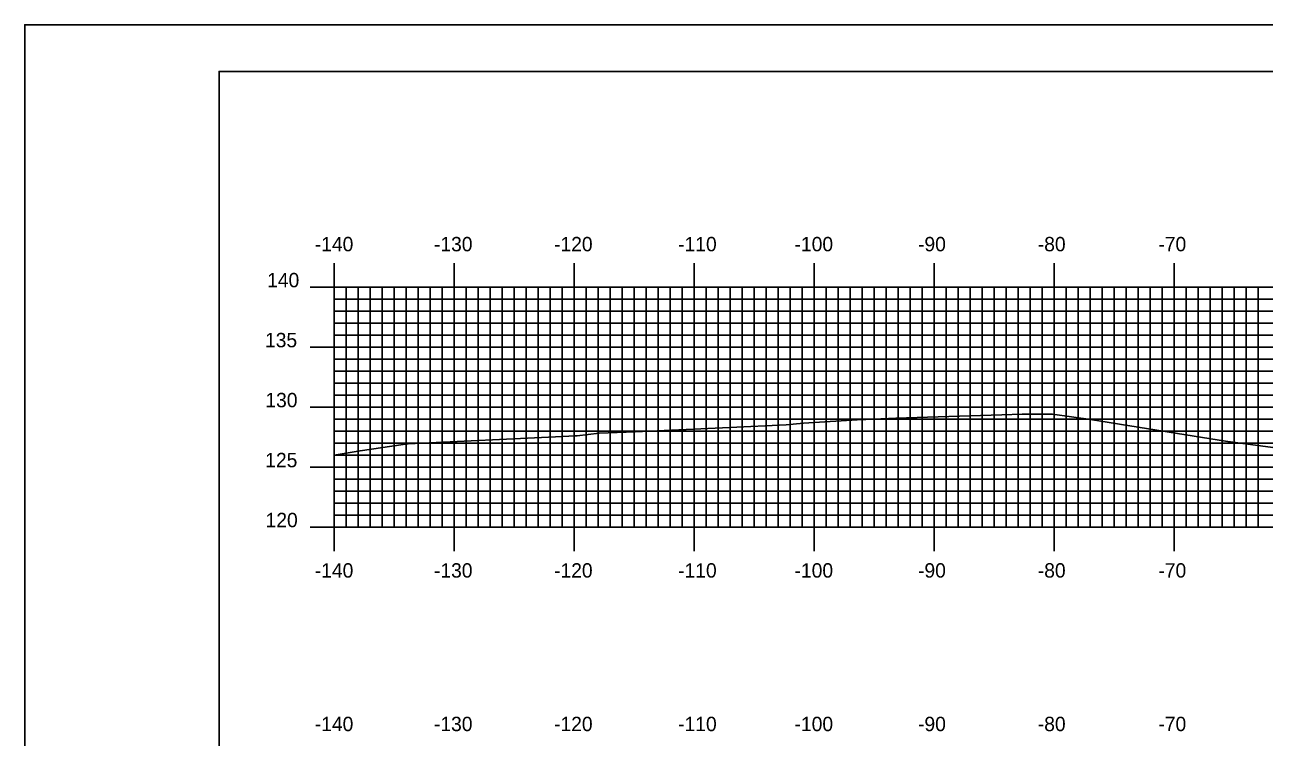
# Model space of a CAD drawing. Extents: x 841388 to 841731, y 363538 to 363758.
# Drawn here: x 841388.1 to 841491.4, y 363698.2 to 363757.6 of the extents above; entities that cross this region are included whole.
import ezdxf

# ---------------------------------------------------------------- set-up
doc = ezdxf.new("R2010")
doc.units = 0
for name, color, linetype in [('BORDER', 7, 'Continuous'), ('H_V ANNOTATION', 7, 'Continuous'), ('M_Roadway_Centerline', 7, 'Continuous'), ('MAJOR', 7, 'Continuous'), ('MINOR', 7, 'Continuous'), ('PLOT BOUNDARY', 7, 'Continuous'), ('S_Roadway_Centerline', 7, 'Continuous')]:
    doc.layers.add(name, color=color, linetype=linetype)

msp = doc.modelspace()

# ---------------------------------------------------------------- linework, layer by layer
at = {"layer": 'BORDER'}
msp.add_lwpolyline([(841404.26, 363543.72), (841724.26, 363543.72), (841724.26, 363753.72), (841404.26, 363753.72)], close=True, dxfattribs=at)
at = {"layer": 'MAJOR'}
for p, q in [((841413.86, 363737.73), (841413.86, 363735.72)), ((841423.86, 363737.73), (841423.86, 363735.72)), ((841433.86, 363737.73), (841433.86, 363735.72)), ((841443.86, 363737.73), (841443.86, 363735.72)), ((841453.86, 363737.73), (841453.86, 363735.72)), ((841463.86, 363737.73), (841463.86, 363735.72)), ((841473.86, 363737.73), (841473.86, 363735.72)), ((841483.86, 363737.73), (841483.86, 363735.72)), ((841411.85, 363735.72), (841413.86, 363735.72)), ((841413.86, 363735.72), (841693.86, 363735.72)), ((841413.86, 363715.72), (841413.86, 363735.72)), ((841413.86, 363715.72), (841413.86, 363735.72)), ((841413.86, 363735.72), (841693.86, 363735.72)), ((841423.86, 363715.72), (841423.86, 363735.72)), ((841433.86, 363715.72), (841433.86, 363735.72)), ((841443.86, 363715.72), (841443.86, 363735.72)), ((841453.86, 363715.72), (841453.86, 363735.72)), ((841463.86, 363715.72), (841463.86, 363735.72)), ((841473.86, 363715.72), (841473.86, 363735.72)), ((841483.86, 363715.72), (841483.86, 363735.72)), ((841411.85, 363730.72), (841413.86, 363730.72)), ((841413.86, 363730.72), (841693.86, 363730.72)), ((841411.85, 363725.72), (841413.86, 363725.72)), ((841413.86, 363725.72), (841693.86, 363725.72)), ((841411.85, 363720.72), (841413.86, 363720.72)), ((841413.86, 363720.72), (841693.86, 363720.72)), ((841411.85, 363715.72), (841413.86, 363715.72)), ((841413.86, 363715.72), (841693.86, 363715.72)), ((841413.86, 363715.72), (841693.86, 363715.72)), ((841413.86, 363713.72), (841413.86, 363715.72)), ((841423.86, 363713.72), (841423.86, 363715.72)), ((841433.86, 363713.72), (841433.86, 363715.72)), ((841443.86, 363713.72), (841443.86, 363715.72)), ((841453.86, 363713.72), (841453.86, 363715.72)), ((841463.86, 363713.72), (841463.86, 363715.72)), ((841473.86, 363713.72), (841473.86, 363715.72)), ((841483.86, 363713.72), (841483.86, 363715.72))]:
    msp.add_line(p, q, dxfattribs=at)
at = {"layer": 'MINOR'}
for p, q in [((841414.86, 363715.72), (841414.86, 363735.72)), ((841415.86, 363715.72), (841415.86, 363735.72)), ((841416.86, 363715.72), (841416.86, 363735.72)), ((841417.86, 363715.72), (841417.86, 363735.72)), ((841418.86, 363715.72), (841418.86, 363735.72)), ((841419.86, 363715.72), (841419.86, 363735.72)), ((841420.86, 363715.72), (841420.86, 363735.72)), ((841421.86, 363715.72), (841421.86, 363735.72)), ((841422.86, 363715.72), (841422.86, 363735.72)), ((841424.86, 363715.72), (841424.86, 363735.72)), ((841425.86, 363715.72), (841425.86, 363735.72)), ((841426.86, 363715.72), (841426.86, 363735.72)), ((841427.86, 363715.72), (841427.86, 363735.72)), ((841428.86, 363715.72), (841428.86, 363735.72)), ((841429.86, 363715.72), (841429.86, 363735.72)), ((841430.86, 363715.72), (841430.86, 363735.72)), ((841431.86, 363715.72), (841431.86, 363735.72)), ((841432.86, 363715.72), (841432.86, 363735.72)), ((841434.86, 363715.72), (841434.86, 363735.72)), ((841435.86, 363715.72), (841435.86, 363735.72)), ((841436.86, 363715.72), (841436.86, 363735.72)), ((841437.86, 363715.72), (841437.86, 363735.72)), ((841438.86, 363715.72), (841438.86, 363735.72)), ((841439.86, 363715.72), (841439.86, 363735.72)), ((841440.86, 363715.72), (841440.86, 363735.72)), ((841441.86, 363715.72), (841441.86, 363735.72)), ((841442.86, 363715.72), (841442.86, 363735.72)), ((841444.86, 363715.72), (841444.86, 363735.72)), ((841445.86, 363715.72), (841445.86, 363735.72)), ((841446.86, 363715.72), (841446.86, 363735.72)), ((841447.86, 363715.72), (841447.86, 363735.72)), ((841448.86, 363715.72), (841448.86, 363735.72)), ((841449.86, 363715.72), (841449.86, 363735.72)), ((841450.86, 363715.72), (841450.86, 363735.72)), ((841451.86, 363715.72), (841451.86, 363735.72)), ((841452.86, 363715.72), (841452.86, 363735.72)), ((841454.86, 363715.72), (841454.86, 363735.72)), ((841455.86, 363715.72), (841455.86, 363735.72)), ((841456.86, 363715.72), (841456.86, 363735.72)), ((841457.86, 363715.72), (841457.86, 363735.72)), ((841458.86, 363715.72), (841458.86, 363735.72)), ((841459.86, 363715.72), (841459.86, 363735.72)), ((841460.86, 363715.72), (841460.86, 363735.72)), ((841461.86, 363715.72), (841461.86, 363735.72)), ((841462.86, 363715.72), (841462.86, 363735.72)), ((841464.86, 363715.72), (841464.86, 363735.72)), ((841465.86, 363715.72), (841465.86, 363735.72)), ((841466.86, 363715.72), (841466.86, 363735.72)), ((841467.86, 363715.72), (841467.86, 363735.72)), ((841468.86, 363715.72), (841468.86, 363735.72)), ((841469.86, 363715.72), (841469.86, 363735.72)), ((841470.86, 363715.72), (841470.86, 363735.72)), ((841471.86, 363715.72), (841471.86, 363735.72)), ((841472.86, 363715.72), (841472.86, 363735.72)), ((841474.86, 363715.72), (841474.86, 363735.72)), ((841475.86, 363715.72), (841475.86, 363735.72)), ((841476.86, 363715.72), (841476.86, 363735.72)), ((841477.86, 363715.72), (841477.86, 363735.72)), ((841478.86, 363715.72), (841478.86, 363735.72)), ((841479.86, 363715.72), (841479.86, 363735.72)), ((841480.86, 363715.72), (841480.86, 363735.72)), ((841481.86, 363715.72), (841481.86, 363735.72)), ((841482.86, 363715.72), (841482.86, 363735.72)), ((841484.86, 363715.72), (841484.86, 363735.72)), ((841485.86, 363715.72), (841485.86, 363735.72)), ((841486.86, 363715.72), (841486.86, 363735.72)), ((841487.86, 363715.72), (841487.86, 363735.72)), ((841488.86, 363715.72), (841488.86, 363735.72)), ((841489.86, 363715.72), (841489.86, 363735.72)), ((841490.86, 363715.72), (841490.86, 363735.72)), ((841413.86, 363734.72), (841693.86, 363734.72)), ((841413.86, 363734.72), (841415.86, 363734.72)), ((841413.86, 363733.72), (841693.86, 363733.72)), ((841413.86, 363733.72), (841415.86, 363733.72)), ((841413.86, 363732.72), (841693.86, 363732.72)), ((841413.86, 363732.72), (841415.86, 363732.72)), ((841413.86, 363731.72), (841693.86, 363731.72)), ((841413.86, 363731.72), (841415.86, 363731.72)), ((841413.86, 363729.72), (841693.86, 363729.72)), ((841413.86, 363729.72), (841415.86, 363729.72)), ((841413.86, 363728.72), (841693.86, 363728.72)), ((841413.86, 363728.72), (841415.86, 363728.72)), ((841413.86, 363727.72), (841693.86, 363727.72)), ((841413.86, 363727.72), (841415.86, 363727.72)), ((841413.86, 363726.72), (841693.86, 363726.72)), ((841413.86, 363726.72), (841415.86, 363726.72)), ((841413.86, 363724.72), (841693.86, 363724.72)), ((841413.86, 363724.72), (841415.86, 363724.72)), ((841413.86, 363723.72), (841693.86, 363723.72)), ((841413.86, 363723.72), (841415.86, 363723.72)), ((841413.86, 363722.72), (841693.86, 363722.72)), ((841413.86, 363722.72), (841415.86, 363722.72)), ((841413.86, 363721.72), (841693.86, 363721.72)), ((841413.86, 363721.72), (841415.86, 363721.72)), ((841413.86, 363719.72), (841693.86, 363719.72)), ((841413.86, 363719.72), (841415.86, 363719.72)), ((841413.86, 363718.72), (841693.86, 363718.72)), ((841413.86, 363718.72), (841415.86, 363718.72)), ((841413.86, 363717.72), (841693.86, 363717.72)), ((841413.86, 363717.72), (841415.86, 363717.72)), ((841413.86, 363716.72), (841693.86, 363716.72)), ((841413.86, 363716.72), (841415.86, 363716.72))]:
    msp.add_line(p, q, dxfattribs=at)
at = {"layer": 'PLOT BOUNDARY'}
msp.add_lwpolyline([(841388.07, 363537.6), (841728.07, 363537.6), (841728.07, 363757.6), (841388.07, 363757.6)], close=True, dxfattribs=at)
at = {"layer": 'S_Roadway_Centerline'}
msp.add_lwpolyline([(841413.86, 363721.72), (841416.02, 363722.09), (841419.61, 363722.61), (841420.02, 363722.66), (841432.89, 363723.27), (841433.95, 363723.33), (841434.1, 363723.34), (841435.94, 363723.55), (841438.94, 363723.67), (841446.84, 363724.03), (841451.53, 363724.25), (841452.97, 363724.39), (841457.88, 363724.71), (841458.15, 363724.7), (841460.66, 363724.81), (841469.48, 363725.1), (841471.2, 363725.15), (841473.72, 363725.15), (841476.88, 363724.69), (841484.84, 363723.43), (841488.13, 363722.89), (841497.5, 363721.63)], dxfattribs=at)

# ---------------------------------------------------------------- texts
at = {"layer": 'H_V ANNOTATION'}
for s, p in [('-140', (841412.24, 363738.72)), ('-130', (841422.17, 363738.72)), ('-120', (841432.18, 363738.72)), ('-110', (841442.52, 363738.72)), ('-100', (841452.22, 363738.72)), ('-90', (841462.51, 363738.72)), ('-80', (841472.49, 363738.72)), ('-70', (841482.54, 363738.72)), ('140', (841408.27, 363735.72)), ('135', (841408.09, 363730.72)), ('130', (841408.12, 363725.72)), ('125', (841408.11, 363720.72)), ('120', (841408.14, 363715.72)), ('-140', (841412.24, 363711.52)), ('-130', (841422.17, 363711.52)), ('-120', (841432.18, 363711.52)), ('-110', (841442.52, 363711.52)), ('-100', (841452.22, 363711.52)), ('-90', (841462.51, 363711.52)), ('-80', (841472.49, 363711.52)), ('-70', (841482.54, 363711.52)), ('-140', (841412.24, 363698.72)), ('-130', (841422.17, 363698.72)), ('-120', (841432.18, 363698.72)), ('-110', (841442.52, 363698.72)), ('-100', (841452.22, 363698.72)), ('-90', (841462.51, 363698.72)), ('-80', (841472.49, 363698.72)), ('-70', (841482.54, 363698.72))]:
    msp.add_text(s, height=1.2, dxfattribs=at).set_placement(p)
at = {"layer": 'M_Roadway_Centerline'}
for s, p in [('C', (841457.88, 363724.71)), ('L', (841457.88, 363724.7)), ('C', (841435.93, 363723.55)), ('L', (841435.94, 363723.55))]:
    msp.add_text(s, height=0.0146, dxfattribs=at).set_placement(p)
at = {"layer": 'MAJOR'}
msp.add_text('-', height=0.012, dxfattribs=at).set_placement((841413.85, 363715.72))

doc.saveas('drawing.dxf')
